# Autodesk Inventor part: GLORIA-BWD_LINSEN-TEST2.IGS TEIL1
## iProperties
Created: 2005-04
Part Number: GLORIA-BWD_LINSEN-TEST2.IGS TEIL1
Document SubType Name: Modeling
Designer: Nordmeyer
Manufacturer: Standard
Standards Organization: Custom
Author: Nordmeyer
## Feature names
1. Erst1
